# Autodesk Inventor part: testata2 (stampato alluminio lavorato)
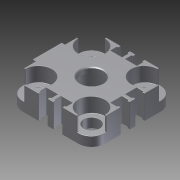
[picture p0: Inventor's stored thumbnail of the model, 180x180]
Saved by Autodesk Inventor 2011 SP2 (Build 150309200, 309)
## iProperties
Created: 2018-03
Part Number: testata2 (stampato alluminio lavorato)
Document SubType Name: Modeling
Designer: 18619647
Density: 1 g/cm^3
Author: 18619647
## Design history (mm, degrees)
sketch "Schizzo1"
  geometry: L1 (0, 0)-(25, 0); L2 (25, 0)-(25, 25); L3 (25, 25)-(-25, 25); L4 (-25, 25)-(-25, -25); L5 (-25, -25)-(25, -25); L6 (25, -25)-(25, 0); C1 r 15.75 at (0, 0); 1 further point
  constraints: 12 end point, 2 parallel, 2 perpendicular, 1 centre point, 1 coincident, 1 horizontal
  dimensions: "d0" = 31.5 diameter of C1; "d1" = 25 distance of L1.start L1.end; "d2" = 25 distance of L1.end L2.end; "d3" = 50 distance of L2.end L3.end; "d4" = 50 distance of L3.end L4.end; "d5" = 50 distance of L4.end L5.end
extrude "Estrusione1" new body sketch "Schizzo1" distance "d6" = 14.4; taper "d7" = 0 deg
fillet "Raccordo1" dims "d8" = 8
sketch "Schizzo2"
  geometry: L1 (-25, -17)-(-25, 17) reference; L2 (-17, 25)-(17, 25) reference; L3 (-25, 0)-(-27, 0); L4 (-27, 0)-(-27, -8.8); L5 (-27, -8.8)-(-25, -8.8); L6 (-25, -8.8)-(-25, 8.8); L7 (-25, 8.8)-(-27, 8.8); L8 (-27, 8.8)-(-27, 0)
  constraints: 12 end point, 2 parallel, 2 perpendicular, 2 point on line, 1 midpoint
  dimensions: "d9" = 2 distance of L3.start L3.end; "d10" = 8.8 distance of L3.end L4.end; "d11" = 2 distance of L4.end L5.end; "d12" = 17.6 distance of L5.end L6.end
extrude "Estrusione2" join sketch "Schizzo2" distance "d13" = 14.4; taper "d14" = 0 deg
hole "Hole1" diameter "d17" = 9.5; stored, may be unused: countersink angle "d21" = 82 deg, drill point angle "d23" = 118 deg; dims "d15" = 8.9, "d16" = 8.9, "d18" = 6, "d19" = 3.023, "d20" = 2, "d22" = 8.2
node "Piano di lavoro1"
sketch "Schizzo3"
  geometry: L1 (1.75, -25)-(1.75, -23.5); L2 (1.75, -23.5)-(1, -23.5); L3 (1, -23.5)-(1, -19.5); L4 (1, -19.5)-(8, -19.5); L5 (8, -19.5)-(8, -23.5); L6 (8, -23.5)-(7.25, -23.5); L7 (7.25, -23.5)-(7.25, -25); L8 (-1, -19.5)-(-8, -19.5); L9 (-1, -23.5)-(-1, -19.5); L10 (-1.75, -23.5)-(-1, -23.5); L11 (-1.75, -25)-(-1.75, -23.5); L12 (-8, -19.5)-(-8, -23.5); L13 (-8, -23.5)-(-7.25, -23.5); L14 (-7.25, -23.5)-(-7.25, -25); L15 (-17, 25)-(17, 25) reference; L16 (25, 17)-(25, 8.8) reference; L17 (17, -25)-(-17, -25) reference; L18 (-25, -17)-(-25, 17) reference; L19 (7.25, -25)-(1.75, -25); L20 (-1.75, -25)-(-7.25, -25); L21 (25, 8.8)-(27, 8.8) reference; L22 (27, 8.8)-(27, -8.8) reference; L23 (27, -8.8)-(25, -8.8) reference; L24 (25, -8.8)-(25, -17) reference; C1 r 4.75 at (16.1, -16.1) reference; A1 r 8 centre (-17, 17) between (-17, 25) and (-25, 17) reference; A2 r 8 centre (17, 17) between (25, 17) and (17, 25) reference; A3 r 8 centre (17, -17) between (17, -25) and (25, -17) reference; A4 r 8 centre (-17, -17) between (-25, -17) and (-17, -25) reference
  constraints: 32 end point, 2 collinear, 1 parallel, 1 perpendicular
  dimensions: "d30" = 1.5 distance of L1.start L1.end; "d31" = 0.75 distance of L1.end L2.end; "d32" = 4 distance of L2.end L3.end; "d33" = 7 distance of L3.end L4.end; "d34" = 4 distance of L4.end L5.end; "d35" = 0.75 distance of L5.end L6.end
extrude "Estrusione3" cut sketch "Schizzo3" distance "d36" = 56; taper "d37" = 0 deg
pattern_circular "Serie circolare1" dims angle "d39" = 180 deg
pattern_linear "Serie rettangolare1" dims "d43" = 32.2, "d46" = 32.2
sketch "Schizzo5"
  geometry: C1 r 16 at (0, 0); 1 further point
  constraints: 1 centre point, 1 coincident
  dimensions: "d64" = 32 diameter of C1
extrude "Estrusione4" join sketch "Schizzo5" distance "d65" = 0.8; taper "d66" = 0 deg
sketch "Schizzo6"
  geometry: C1 r 16 at (0, 0) reference; C2 r 17.5 at (0, 0); C3 r 16 at (0, 0)
  constraints: 2 centre point, 2 coincident
  dimensions: "d67" = 35 diameter of C2; "d68" = 32 diameter of C3
extrude "Estrusione5" cut sketch "Schizzo6" distance "d69" = 0.7; taper "d70" = 0 deg
sketch "Schizzo7"
  geometry: C1 r 16 at (0, 0) reference; C2 r 10.5 at (0, 0)
  constraints: 1 centre point, 1 coincident
  dimensions: "d71" = 21 diameter of C2
extrude "Estrusione6" cut sketch "Schizzo7" distance "d72" = 4; taper "d73" = 0 deg
sketch "Schizzo9"
  geometry: L1 (0, 0)-(14, 0); C1 r 16 at (0, 0) reference
  constraints: 2 end point, 1 horizontal
  dimensions: "d77" = 14 distance of L1.start L1.end
hole "Hole3" sketch "Schizzo9" at (14, 0) diameter "d78" = 2; stored, may be unused: countersink angle "d82" = 90 deg, drill point angle "d84" = 0 deg; dims "d79" = 6, "d80" = 4, "d81" = 2, "d83" = 8
hole "Hole4" diameter "d87" = 7.5; stored, may be unused: countersink angle "d91" = 90 deg, drill point angle "d93" = 0 deg; dims "d85" = 7.2, "d86" = 8.8, "d88" = 6, "d89" = 4, "d90" = 2, "d92" = 14
sketch "Schizzo10"
  geometry: C1 r 3.75 at (-7.2, 8.8) reference; C2 r 4.1 at (-7.2, 8.8); 1 further point
  constraints: 1 centre point, 1 coincident
  dimensions: "d94" = 8.2 diameter of C2
extrude "Estrusione8" cut sketch "Schizzo10" distance "d95" = 12; taper "d96" = 0 deg
sketch "Schizzo11"
  geometry: C1 r 4.1 at (-7.2, 8.8) reference; C2 r 4.5 at (-7.2, 8.8); 1 further point
  constraints: 1 centre point, 1 coincident
  dimensions: "d97" = 9 diameter of C2
extrude "Estrusione9" cut sketch "Schizzo11" distance "d98" = 12; taper "d99" = 0 deg
feature "Filettatura7" dims "d100" = 10, "d101" = 2
chamfer "Smusso1" distance "d102" = 0.5; stored, may be unused: second distance "d103" = 2, angle "d104" = 45 deg
sketch "Schizzo12"
  geometry: C1 r 10.5 at (0, 0) reference; C2 r 8.25 at (0, 0)
  constraints: 1 centre point, 1 coincident
  dimensions: "d105" = 16.5 diameter of C2
extrude "Estrusione10" cut sketch "Schizzo12" distance "d106" = 4; taper "d107" = 0 deg
pattern_circular "Serie circolare2" dims angle "d109" = 180 deg
sketch "Schizzo13"
  geometry: L1 (-25, -17)-(-25, -8.8) reference; L2 (-8, 23.5)-(-7.25, 23.5) reference; L3 (-16.1, -24.1)-(-16.1, -28.112); L4 (-16.1, -28.112)-(-34.474, -28.112); L5 (-34.474, -28.112)-(-30.523, -16.1); L6 (-30.523, -16.1)-(-24.1, -16.1); C1 r 4.75 at (-16.1, -16.1) reference; A1 r 8 centre (-16.1, -16.1) between (-16.1, -24.1) and (-24.1, -16.1); 1 further point
  constraints: 8 end point, 3 perpendicular, 2 point on circle, 1 centre point, 1 coincident
  dimensions: "d111" = 16 diameter of A1
extrude "Estrusione11" cut sketch "Schizzo13" distance "d112" = 8.8; taper "d113" = 0 deg
mirror "Specchio2"
mirror "Specchio3"
fillet "Raccordo2" dims "d114" = 0.2
sketch "Schizzo14"
  geometry: C1 r 3 at (0, 0); 1 further point
  constraints: 1 centre point, 1 coincident
  dimensions: "d115" = 6 diameter of C1
extrude "Estrusione12" cut sketch "Schizzo14" distance "d116" = 4.5; taper "d117" = 0 deg
fillet "Raccordo3" dims "d118" = 0.2
sketch "Schizzo15"
  geometry: C1 r 10.5 at (0, 0) reference; C2 r 9 at (0, 0)
  constraints: 1 centre point, 1 coincident
  dimensions: "d119" = 18 diameter of C2
extrude "Estrusione13" cut sketch "Schizzo15" distance "d120" = 8; taper "d121" = 0 deg
sketch "Schizzo16"
  geometry: C1 r 9 at (0, 0) reference; C2 r 6.9 at (0, 0)
  constraints: 1 centre point, 1 coincident
  dimensions: "d122" = 13.8 diameter of C2
extrude "Estrusione14" cut sketch "Schizzo16" stored distance "d123" = 6; taper "d124" = 0 deg
chamfer "Smusso2" distance "d125" = 0.5; stored, may be unused: second distance "d126" = 2, angle "d127" = 45 deg
node "Solido1"
node "Piano di lavoro2"
node "Proietta spigoli di taglio1"
other parameters: "d28" = 28
